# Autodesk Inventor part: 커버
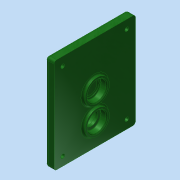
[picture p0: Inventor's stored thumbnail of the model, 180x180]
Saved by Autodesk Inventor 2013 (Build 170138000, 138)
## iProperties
Created: 2016-02
Part Number: 커버
Material: 알루미늄 6061
Document SubType Name: Modeling
Designer: mduedu
Density: 2.71 g/cm^3
Author: mduedu
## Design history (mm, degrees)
sketch "스케치1"
  geometry: L1 (63, 47)-(-47, 47); L2 (-47, 47)-(-47, -47); L3 (-47, -47)-(63, -47); L4 (63, -47)-(63, 47); 2 further points
  constraints: 8 end point, 2 parallel, 1 horizontal, 1 horizontal alignment, 1 midpoint, 1 perpendicular
  dimensions: "d102" = 94 distance of L3.end L1.start; "d104" = 47 distance from line of L2 point (0, 0); "d105" = 110 distance of L1.start L1.end
extrude "돌출1" new body sketch "스케치1" distance "d1" = 10; taper "d2" = 0 deg
sketch "스케치2"
  geometry: C1 r 14 at (0, 11); 1 further point
  constraints: 1 centre point, 1 vertical alignment
  dimensions: "d3" = 28 diameter of C1; "d6" = 11 distance of C1.centre point (0, 0)
extrude "돌출2" join sketch "스케치2" distance "d7" = 3; taper "d8" = 0 deg
sketch "스케치3"
  geometry: C1 r 14 at (0, -20); 1 further point
  constraints: 1 centre point, 1 vertical alignment
  dimensions: "d9" = 28 diameter of C1; "d10" = 20 distance of C1.centre point (0, 0)
extrude "돌출3" join sketch "스케치3" distance "d11" = 3; taper "d12" = 0 deg
hole "구멍1" diameter "d15" = 22; stored, may be unused: countersink angle "d19" = 90 deg, drill point angle "d21" = 0 deg; dims "d13" = 10, "d14" = 10, "d16" = 6, "d17" = 4, "d18" = 2, "d20" = 7
hole "구멍2" diameter "d24" = 18; stored, may be unused: countersink angle "d28" = 90 deg, drill point angle "d30" = 0 deg; dims "d22" = 10, "d23" = 10, "d25" = 6, "d26" = 4, "d27" = 2, "d29" = 1
hole "구멍3" diameter "d33" = 22; stored, may be unused: countersink angle "d37" = 90 deg, drill point angle "d39" = 0 deg; dims "d34" = 6, "d35" = 4, "d36" = 2, "d38" = 7, "d73" = 10, "d74" = 10
sketch "스케치4"
  geometry: C1 r 14 at (0, -20) reference; C2 r 18 at (0, -20); 1 further point
  constraints: 1 centre point, 1 coincident
  dimensions: "d40" = 36 diameter of C2
extrude "돌출4" join sketch "스케치4" distance "d41" = 4; taper "d42" = 0 deg
hole "구멍4" diameter "d45" = 22; stored, may be unused: countersink angle "d49" = 90 deg, drill point angle "d51" = 0 deg; dims "d43" = 10, "d44" = 10, "d46" = 6, "d47" = 4, "d48" = 2, "d50" = 7
hole "구멍5" diameter "d54" = 15; stored, may be unused: countersink angle "d58" = 90 deg, drill point angle "d60" = 0 deg; dims "d52" = 10, "d53" = 10, "d55" = 6, "d56" = 4, "d57" = 2, "d59" = 7
fillet "모깎기1" dims "d61" = 0.3
fillet "모깎기2" dims "d62" = 2
chamfer "모따기1" distance "d63" = 1; stored, may be unused: second distance "d64" = 2, angle "d65" = 45 deg
fillet "모깎기6" dims "d88" = 2
fillet "모깎기4" dims "d75" = 2
sketch "스케치9"
  geometry: L1 (47, 63)-(47, -47) reference; L2 (-47, 63)-(47, 63) reference; L3 (-47, -47)-(-47, 63) reference; L4 (47, -47)-(-47, -47) reference; L5 (37, 53)-(37, -37); L6 (37, -37)-(-37, -37); L7 (-37, -37)-(-37, 53); L8 (-37, 53)-(37, 53); C1 r 20 at (0, -20) reference; 5 further points
  constraints: 8 end point, 4 coincident, 3 other
  dimensions: "d107" = 10 distance between parallel lines of L8 L2
hole "구멍7" sketch "스케치9" at (-37, 53), (37, 53), (37, -37), (-37, -37) diameter "d108" = 4.5; stored, may be unused: countersink angle "d112" = 90 deg, drill point angle "d114" = 118 deg; dims "d109" = 6, "d110" = 8, "d111" = 4.6, "d113" = 8
fillet "모깎기8" dims "d106" = 3
fillet "모깎기9" dims "d115" = 3
node "솔리드1"
node "투영된 루프2"
